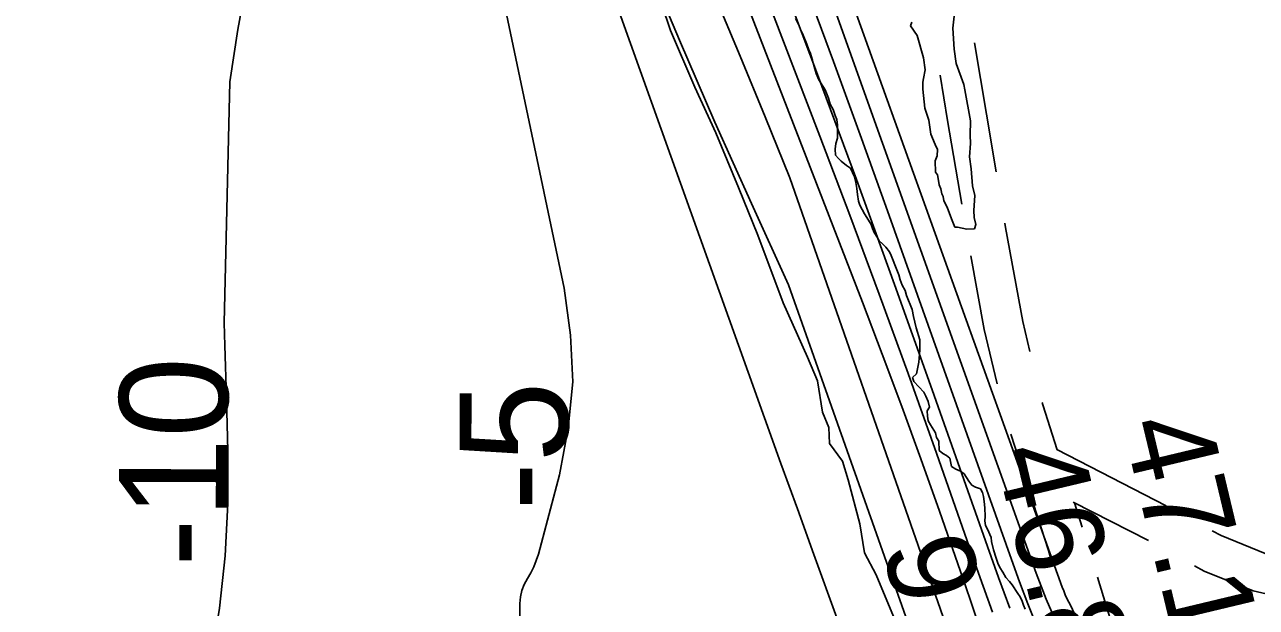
# Model space of a CAD drawing. Extents: x 3250478 to 3288318, y 788638 to 816472.
# Drawn here: x 3278256 to 3279198, y 795831 to 796276 of the extents above; entities that cross this region are included whole.
import ezdxf

# ---------------------------------------------------------------- set-up
doc = ezdxf.new("R2010")
doc.units = 0
for name, color, linetype in [('V-RIVR-EDGE', 7, 'Continuous'), ('V-RIVR-RANG', 7, 'Continuous'), ('V-ROAD-CNTR', 7, 'Continuous'), ('V-SITE-VEGE', 7, 'Continuous'), ('V-TOPO-DPTH', 7, 'Continuous'), ('V-TOPO-MAJR', 7, 'Continuous'), ('V-TOPO-MINR', 7, 'Continuous'), ('V-TOPO-MINR-IDEN', 7, 'Continuous'), ('V-TOPO-WATR', 7, 'Continuous')]:
    doc.layers.add(name, color=color, linetype=linetype)

msp = doc.modelspace()

# ---------------------------------------------------------------- linework, layer by layer
at = {"layer": 'V-RIVR-EDGE'}
msp.add_lwpolyline([(3278928.01, 795805.46), (3278907.27, 795855.5), (3278898.18, 795872.47), (3278894.76, 795894.65), (3278885.71, 795928.14), (3278881.4, 795942.5), (3278871.44, 795956), (3278871.03, 795968.17), (3278866.28, 795979.92), (3278862.43, 796003.83), (3278854.65, 796022.11), (3278836.06, 796063.45), (3278816.63, 796115.23), (3278801.94, 796151.77), (3278784.66, 796193.55), (3278768.66, 796228.36), (3278750.08, 796271.87), (3278730.66, 796329.3)], dxfattribs=at)
at = {"layer": 'V-ROAD-CNTR'}
for p, q in [((3279045.35, 795951.31), (3279129, 795908.39)), ((3279057.85, 795911.18), (3279115.31, 795881.7))]:
    msp.add_line(p, q, dxfattribs=at)
for points in [[(3278982.49, 796262.43), (3278991.43, 796207.89), (3278998.93, 796163.79)], [(3278956.16, 796237.58), (3278961.84, 796202.95), (3278972.72, 796138.96)], [(3279005.63, 796124.36), (3279006.19, 796121.08), (3279019.24, 796049.31), (3279024.75, 796026.23)], [(3278979.61, 796099.56), (3278989.87, 796043.14), (3278999.78, 796001.66)], [(3279034.05, 795987.33), (3279034.49, 795985.47), (3279045.56, 795951.2)], [(3279010.2, 795963.07), (3279038.88, 795874.29), (3279040.83, 795867.87)], [(3279058.69, 795910.54), (3279064.64, 795892.13)], [(3279164.13, 795889.26), (3279170.85, 795885.55), (3279204.47, 795871.99), (3279259.09, 795859.33)], [(3279150.43, 795862.56), (3279157.93, 795858.41), (3279195.42, 795843.29), (3279245.1, 795831.78)], [(3279076.45, 795853.91), (3279103.45, 795765.39), (3279105.45, 795758.21)]]:
    msp.add_lwpolyline(points, dxfattribs=at)
at = {"layer": 'V-SITE-VEGE'}
for p, q in [((3278845.4, 796280.87), (3278848.32, 796275.45)), ((3278933.44, 796275.31), (3278934.43, 796278.04)), ((3278967.18, 796284.97), (3278965.9, 796273.58)), ((3278848.32, 796275.45), (3278849.33, 796272.42)), ((3278849.33, 796272.42), (3278851.29, 796268.2)), ((3278851.29, 796268.2), (3278854.25, 796261.24)), ((3278938.52, 796267.9), (3278933.44, 796275.31)), ((3278943.35, 796250.76), (3278938.52, 796267.9)), ((3278965.9, 796273.58), (3278966.93, 796257.41)), ((3278854.25, 796261.24), (3278855.6, 796257)), ((3278855.6, 796257), (3278856.91, 796254.29)), ((3278966.93, 796257.41), (3278968.33, 796246.65)), ((3278856.91, 796254.29), (3278858.59, 796249.13)), ((3278858.59, 796249.13), (3278859.3, 796246.09)), ((3278944.71, 796241.62), (3278943.35, 796250.76)), ((3278859.3, 796246.09), (3278861.35, 796238.81)), ((3278861.35, 796238.81), (3278863.33, 796233.98)), ((3278943.28, 796235.09), (3278944.71, 796241.62)), ((3278968.33, 796246.65), (3278974.21, 796230.61)), ((3278863.33, 796233.98), (3278866.54, 796229.18)), ((3278866.54, 796229.18), (3278868.15, 796226.47)), ((3278942.82, 796232.38), (3278943.28, 796235.09)), ((3278942.98, 796226.98), (3278942.82, 796232.38)), ((3278974.21, 796230.61), (3278974.88, 796226.31)), ((3278868.15, 796226.47), (3278870.79, 796220.13)), ((3278870.79, 796220.13), (3278872.15, 796215.58)), ((3278944.5, 796212.44), (3278942.98, 796226.98)), ((3278974.88, 796226.31), (3278979.37, 796202.68)), ((3278872.15, 796215.58), (3278874.41, 796211.36)), ((3278874.41, 796211.36), (3278875.77, 796206.81)), ((3278947.47, 796203.34), (3278944.5, 796212.44)), ((3278875.77, 796206.81), (3278877.09, 796203.79)), ((3278877.09, 796203.79), (3278877.52, 796199.52)), ((3278948.88, 796192.58), (3278947.47, 796203.34)), ((3278979.37, 796202.68), (3278979.15, 796191.87)), ((3278877.52, 796199.52), (3278877.65, 796195.24)), ((3278877.65, 796195.24), (3278877.52, 796189.43)), ((3278952.36, 796184.58), (3278948.88, 796192.58)), ((3278979.15, 796191.87), (3278979.35, 796185.39)), ((3278876.42, 796185.42), (3278875.93, 796181.12)), ((3278877.52, 796189.43), (3278876.42, 796185.42)), ((3278954.09, 796180.85), (3278952.36, 796184.58)), ((3278979.35, 796185.39), (3278978.57, 796175.1)), ((3278875.93, 796181.12), (3278876.07, 796176.53)), ((3278876.07, 796176.53), (3278878.29, 796173.84)), ((3278878.29, 796173.84), (3278880.5, 796171.77)), ((3278952.19, 796172.15), (3278953.7, 796175.98)), ((3278952.45, 796163.52), (3278952.19, 796172.15)), ((3278953.7, 796175.98), (3278954.09, 796180.85)), ((3278978.57, 796175.1), (3278979.93, 796165.96)), ((3278880.5, 796171.77), (3278884.57, 796168.52)), ((3278884.57, 796168.52), (3278887.69, 796166.48)), ((3278887.69, 796166.48), (3278890.64, 796159.83)), ((3278954.13, 796161.4), (3278952.45, 796163.52)), ((3278979.93, 796165.96), (3278980.85, 796153.02)), ((3278890.64, 796159.83), (3278891.69, 796155.58)), ((3278891.69, 796155.58), (3278892.44, 796151.01)), ((3278954.8, 796157.1), (3278954.13, 796161.4)), ((3278955.44, 796153.88), (3278954.8, 796157.1)), ((3278956.62, 796150.68), (3278955.44, 796153.88)), ((3278892.44, 796151.01), (3278892.88, 796146.44)), ((3278892.88, 796146.44), (3278893.65, 796141.26)), ((3278957.27, 796146.91), (3278956.62, 796150.68)), ((3278958.41, 796144.79), (3278957.27, 796146.91)), ((3278959.05, 796141.56), (3278958.41, 796144.79)), ((3278980.85, 796153.02), (3278982.7, 796145.51)), ((3278982.7, 796145.51), (3278981.96, 796134.15)), ((3278893.65, 796141.26), (3278894.66, 796138.23)), ((3278894.66, 796138.23), (3278898.22, 796131.6)), ((3278961.35, 796136.77), (3278959.05, 796141.56)), ((3278964.87, 796127.69), (3278961.35, 796136.77)), ((3278898.22, 796131.6), (3278900.14, 796128.91)), ((3278900.14, 796128.91), (3278903.36, 796123.5)), ((3278967.22, 796121.28), (3278964.87, 796127.69)), ((3278981.96, 796134.15), (3278982.12, 796128.75)), ((3278982.12, 796128.75), (3278983.36, 796123.38)), ((3278903.36, 796123.5), (3278904.37, 796120.47)), ((3278904.37, 796120.47), (3278905.69, 796117.45)), ((3278905.69, 796117.45), (3278907.94, 796113.84)), ((3278969.38, 796121.34), (3278967.22, 796121.28)), ((3278976.44, 796119.93), (3278969.38, 796121.34)), ((3278982.38, 796120.11), (3278976.44, 796119.93)), ((3278983.36, 796123.38), (3278982.38, 796120.11)), ((3278907.94, 796113.84), (3278909.56, 796110.83)), ((3278909.56, 796110.83), (3278912.06, 796108.76)), ((3278912.06, 796108.76), (3278914.59, 796106.09)), ((3278914.59, 796106.09), (3278917.46, 796102.5)), ((3278917.46, 796102.5), (3278918.76, 796099.79)), ((3278918.76, 796099.79), (3278923.06, 796088.9)), ((3278923.06, 796088.9), (3278924.41, 796084.96)), ((3278924.41, 796084.96), (3278925.44, 796081.02)), ((3278925.44, 796081.02), (3278927.09, 796077.09)), ((3278927.09, 796077.09), (3278929.36, 796072.87)), ((3278929.36, 796072.87), (3278930.39, 796069.23)), ((3278930.39, 796069.23), (3278934.69, 796058.34)), ((3278934.69, 796058.34), (3278935.76, 796053.18)), ((3278935.76, 796053.18), (3278937.86, 796044.36)), ((3278937.86, 796044.36), (3278940.58, 796035.27)), ((3278940.69, 796031.91), (3278940.52, 796027.31)), ((3278940.58, 796035.27), (3278940.69, 796031.91)), ((3278940.52, 796027.31), (3278939.87, 796018.11)), ((3278939.87, 796018.11), (3278938, 796009.18)), ((3278938, 796009.18), (3278935.03, 796006.34)), ((3278935.03, 796006.34), (3278936.03, 796003.31)), ((3278936.03, 796003.31), (3278943.62, 795995.27)), ((3278943.62, 795995.27), (3278945.24, 795992.27)), ((3278945.24, 795992.27), (3278946.9, 795988.03)), ((3278947.94, 795983.78), (3278946.19, 795980.97)), ((3278946.9, 795988.03), (3278947.94, 795983.78)), ((3278946.19, 795980.97), (3278946.31, 795977)), ((3278946.31, 795977), (3278947.03, 795973.35)), ((3278947.03, 795973.35), (3278948.65, 795970.34)), ((3278948.65, 795970.34), (3278952.51, 795964.03)), ((3278952.51, 795964.03), (3278953.22, 795960.69)), ((3278953.22, 795960.69), (3278955.15, 795957.68)), ((3278955.15, 795957.68), (3278955.36, 795950.65)), ((3278955.36, 795950.65), (3278958.19, 795948.29)), ((3278958.19, 795948.29), (3278960.98, 795946.84)), ((3278960.98, 795946.84), (3278963.49, 795944.78)), ((3278963.49, 795944.78), (3278964.91, 795938.39)), ((3278964.91, 795938.39), (3278968.03, 795936.34)), ((3278968.03, 795936.34), (3278971.74, 795934.92)), ((3278971.74, 795934.92), (3278974.56, 795932.87)), ((3278974.56, 795932.87), (3278978.1, 795927.16)), ((3278978.1, 795927.16), (3278980.33, 795924.17)), ((3278980.33, 795924.17), (3278983.12, 795922.72)), ((3278983.12, 795922.72), (3278986.84, 795921.3)), ((3278986.84, 795921.3), (3278988.45, 795918.59)), ((3278988.45, 795918.59), (3278989.15, 795915.56)), ((3278989.15, 795915.56), (3278989.88, 795911.6)), ((3278989.88, 795911.6), (3278990.33, 795906.72)), ((3278990.53, 795900.3), (3278990.32, 795896.93)), ((3278990.33, 795906.72), (3278990.53, 795900.3)), ((3278990.32, 795896.93), (3278990.74, 795893.27)), ((3278990.74, 795893.27), (3278992.35, 795890.56)), ((3278992.35, 795890.56), (3278994.99, 795884.22)), ((3278994.99, 795884.22), (3278995.39, 795881.17)), ((3278995.39, 795881.17), (3278996.8, 795874.79)), ((3278996.8, 795874.79), (3278998.83, 795868.42)), ((3278998.83, 795868.42), (3279000.17, 795864.48)), ((3279000.17, 795864.48), (3279001.8, 795861.17)), ((3279001.8, 795861.17), (3279004.05, 795857.56)), ((3279004.05, 795857.56), (3279006.31, 795853.65)), ((3279006.31, 795853.65), (3279009.16, 795850.37)), ((3279009.16, 795850.37), (3279011.07, 795847.98)), ((3279011.07, 795847.98), (3279015.55, 795841.39)), ((3279015.55, 795841.39), (3279017.16, 795838.68)), ((3279017.16, 795838.68), (3279018.79, 795835.36)), ((3279018.79, 795835.36), (3279019.8, 795832.33)), ((3279019.8, 795832.33), (3279021.11, 795829.31))]:
    msp.add_line(p, q, dxfattribs=at)
at = {"layer": 'V-TOPO-DPTH'}
for points in [[(3278256.21, 797342.18), (3278275.35, 797265.85), (3278305.03, 797151.19), (3278311.64, 797125.94), (3278318.33, 797100.71), (3278325.16, 797075.51), (3278332.08, 797050.34), (3278404.43, 796789.83), (3278419.79, 796724.19), (3278431.55, 796658.06), (3278437.88, 796591.19), (3278440.59, 796523.83), (3278440.51, 796388.37), (3278419.19, 796272.5), (3278413.15, 796232.57), (3278408.82, 796048.2)], [(3278408.82, 796048.2), (3278413.15, 796232.57), (3278419.19, 796272.5), (3278440.51, 796388.37), (3278440.59, 796523.83), (3278437.88, 796591.19), (3278431.55, 796658.06), (3278419.79, 796724.19), (3278404.43, 796789.83), (3278332.08, 797050.34), (3278325.16, 797075.51), (3278318.33, 797100.71), (3278311.64, 797125.94), (3278305.03, 797151.19), (3278275.35, 797265.85), (3278256.21, 797342.18)], [(3278447.43, 796870.65), (3278485.95, 796794.23), (3278505.7, 796755.1), (3278525.47, 796715.99), (3278545.28, 796676.9), (3278565.12, 796637.83), (3278577, 796614.46), (3278590.65, 796586.95), (3278603.94, 796559.27), (3278616.7, 796531.34), (3278629.1, 796503.24), (3278645.18, 796465.81), (3278649.17, 796456.27), (3278653.05, 796446.68), (3278656.74, 796437.01), (3278660.32, 796427.3), (3278809.31, 796010.55), (3278821.82, 795975.67), (3278834.35, 795940.8), (3278846.95, 795905.96), (3278859.58, 795871.13), (3278877.17, 795822.74)], [(3278447.43, 796870.65), (3278485.95, 796794.23), (3278505.7, 796755.1), (3278525.47, 796715.99), (3278545.28, 796676.9), (3278565.12, 796637.83), (3278577, 796614.46), (3278590.65, 796586.95), (3278603.94, 796559.27), (3278616.7, 796531.34), (3278629.1, 796503.24), (3278645.18, 796465.81), (3278649.17, 796456.27), (3278653.05, 796446.68), (3278656.74, 796437.01), (3278660.32, 796427.3), (3278809.31, 796010.55), (3278821.82, 795975.67), (3278834.35, 795940.8), (3278846.95, 795905.96), (3278859.58, 795871.13), (3278877.17, 795822.74)], [(3279124.26, 795347.76), (3278841.2, 796159.17), (3278822.34, 796205.69), (3278803.22, 796252.1), (3278783.93, 796298.44), (3278760.28, 796354.8), (3278752.57, 796372.86), (3278744.72, 796390.86), (3278736.65, 796408.76), (3278728.44, 796426.59), (3278720.05, 796444.35), (3278711.58, 796462.06), (3278702.98, 796479.71), (3278694.3, 796497.32), (3278630.9, 796624.66), (3278591.38, 796706.33), (3278553.1, 796788.55), (3278516.69, 796871.62)], [(3278408.82, 796048.2), (3278409.32, 796030.93), (3278410.49, 795990.61), (3278411.66, 795950.29), (3278411.5, 795910.07), (3278409.61, 795869.99), (3278405.11, 795830.12), (3278398.88, 795790.39), (3278377.3, 795677.08), (3278388.46, 795413.94), (3278391.9, 795341.73), (3278395.85, 795269.54), (3278400.57, 795197.4), (3278405.8, 795125.29), (3278413.99, 795020.02), (3278415.24, 795000.56), (3278416.12, 794981.09), (3278416.46, 794961.61), (3278416.44, 794942.11), (3278403.87, 794831.33), (3278260.3, 794016.3)], [(3279057.64, 794015.57), (3278260.3, 794016.3), (3278403.87, 794831.33), (3278416.44, 794942.11), (3278416.46, 794961.61), (3278416.12, 794981.09), (3278415.24, 795000.56), (3278413.99, 795020.02), (3278405.8, 795125.29), (3278400.57, 795197.4), (3278395.85, 795269.54), (3278391.9, 795341.73), (3278388.46, 795413.94), (3278377.3, 795677.08), (3278398.88, 795790.39), (3278405.11, 795830.12), (3278409.61, 795869.99), (3278411.5, 795910.07), (3278411.66, 795950.29), (3278410.49, 795990.61), (3278409.32, 796030.93), (3278408.82, 796048.2)]]:
    msp.add_lwpolyline(points, dxfattribs=at)
at = {"layer": 'V-TOPO-MAJR'}
msp.add_lwpolyline([(3279009.39, 795830.14), (3279000.8, 795853.63), (3278992.36, 795877.18), (3278950, 795997), (3278921.22, 796077.55), (3278892.06, 796157.97), (3278862.35, 796238.19), (3278832.27, 796318.27), (3278786.83, 796438), (3278779.1, 796458.08), (3278771.23, 796478.09), (3278763.16, 796498.03), (3278754.96, 796517.92), (3278719.31, 796603.15), (3278692.38, 796665.23), (3278664.36, 796726.8), (3278634.74, 796787.61), (3278604.03, 796847.91)], dxfattribs=at)
at = {"layer": 'V-TOPO-MINR'}
for points in [[(3279349.31, 795186.05), (3279055.96, 795831.78), (3279054.44, 795834.74), (3279053.07, 795837.54), (3279051.78, 795840.37), (3279050.6, 795843.25), (3279049.49, 795846.17), (3278848.07, 796407.24), (3278843.05, 796421.17), (3278838, 796435.1), (3278832.91, 796449.01), (3278827.8, 796462.91), (3278822.65, 796476.8), (3278817.48, 796490.68), (3278812.28, 796504.55), (3278807.06, 796518.41), (3278559.9, 797172.34), (3278391.28, 797782.11)], [(3279148.29, 795205.38), (3278840.15, 796077.38), (3278811.81, 796139.45), (3278783.97, 796201.74), (3278756.91, 796264.37), (3278730.36, 796327.23), (3278695.76, 796410.59), (3278686.79, 796431.9), (3278677.7, 796453.14), (3278668.4, 796474.3), (3278658.97, 796495.39), (3278627.19, 796565.57), (3278601.62, 796621.64), (3278575.84, 796677.62), (3278549.75, 796733.45), (3278523.45, 796789.18), (3278367.78, 797116.74), (3278288.44, 797503.93)], [(3278408.82, 796048.2), (3278413.15, 796232.57), (3278419.19, 796272.5), (3278440.51, 796388.37), (3278440.59, 796523.83), (3278437.88, 796591.19), (3278431.55, 796658.06), (3278419.79, 796724.19), (3278404.43, 796789.83), (3278332.08, 797050.34), (3278325.16, 797075.51), (3278318.33, 797100.71), (3278311.64, 797125.94), (3278305.03, 797151.19), (3278275.35, 797265.85), (3278256.21, 797342.18)], [(3279041.45, 795827.05), (3279037.27, 795836.91), (3279033.36, 795846.87), (3279029.63, 795856.9), (3278883.08, 796267.04), (3278869.89, 796303.72), (3278856.6, 796340.37), (3278843.15, 796376.97), (3278829.61, 796413.53), (3278828.56, 796416.35), (3278815.36, 796451.43), (3278802.02, 796486.45), (3278788.45, 796521.39), (3278774.74, 796556.27), (3278641.92, 796891.12)], [(3279124.26, 795347.76), (3278841.2, 796159.17), (3278822.34, 796205.69), (3278803.22, 796252.1), (3278783.93, 796298.44), (3278760.28, 796354.8), (3278752.57, 796372.86), (3278744.72, 796390.86), (3278736.65, 796408.76), (3278728.44, 796426.59), (3278720.05, 796444.35), (3278711.58, 796462.06), (3278702.98, 796479.71), (3278694.3, 796497.32), (3278630.9, 796624.66), (3278591.38, 796706.33), (3278553.1, 796788.55), (3278516.69, 796871.62)], [(3278634.63, 795777.32), (3278634.82, 795833.63), (3278635.29, 795838.69), (3278636.31, 795843.58), (3278638.16, 795848.21), (3278640.57, 795852.68), (3278643.2, 795857.12), (3278645.52, 795861.7), (3278647.38, 795866.48), (3278648.94, 795871.39), (3278665.05, 795932.16), (3278671.81, 795967.64), (3278675.23, 796003.19), (3278673.64, 796038.88), (3278668.72, 796074.65), (3278605.89, 796372.99), (3278599.03, 796401.59), (3278591.13, 796429.86), (3278581.66, 796457.65), (3278571.15, 796485.12), (3278515.51, 796619.22), (3278483.01, 796699.45), (3278451.43, 796780.03), (3278421.21, 796861.13)], [(3279029.77, 795816.75), (3279023.12, 795833.48), (3279016.75, 795850.33), (3279010.58, 795867.24), (3278917.04, 796130.39), (3278895.93, 796189.27), (3278874.6, 796248.06), (3278852.96, 796306.75), (3278831.1, 796365.35), (3278807.87, 796427.13), (3278797.34, 796454.73), (3278786.64, 796482.27), (3278775.69, 796509.7), (3278764.56, 796537.07), (3278706.54, 796677.93), (3278673.08, 796757.93), (3278639.07, 796837.69)], [(3278996.14, 795826.91), (3278985.53, 795856.8), (3278974.97, 795886.71), (3278953.2, 795948.66), (3278931.55, 796009.47), (3278909.56, 796070.16), (3278887.06, 796130.66), (3278864.22, 796191.03), (3278765.38, 796449.01), (3278760.54, 796461.46), (3278755.63, 796473.88), (3278750.59, 796486.25), (3278745.48, 796498.59), (3278723.55, 796550.8), (3278706.95, 796589.01), (3278689.74, 796626.93), (3278671.6, 796664.42), (3278652.85, 796701.61), (3278635.1, 796735.77), (3278613.16, 796777.79), (3278591.12, 796819.75)], [(3278983.51, 795823.84), (3278979.62, 795835.07), (3278975.72, 795846.29), (3278955.5, 795904.22), (3278941.28, 795944.33), (3278926.78, 795984.35), (3278911.89, 796024.21), (3278896.74, 796063.98), (3278743.46, 796460.17)], [(3278260.3, 794016.3), (3278403.87, 794831.33), (3278416.44, 794942.11), (3278416.46, 794961.61), (3278416.12, 794981.09), (3278415.24, 795000.56), (3278413.99, 795020.02), (3278405.8, 795125.29), (3278400.57, 795197.4), (3278395.85, 795269.54), (3278391.9, 795341.73), (3278388.46, 795413.94), (3278377.3, 795677.08), (3278398.88, 795790.39), (3278405.11, 795830.12), (3278409.61, 795869.99), (3278411.5, 795910.07), (3278411.66, 795950.29), (3278410.49, 795990.61), (3278409.32, 796030.93), (3278408.82, 796048.2)]]:
    msp.add_lwpolyline(points, dxfattribs=at)
at = {"layer": 'V-TOPO-WATR'}
msp.add_lwpolyline([(3278877.17, 795822.74), (3278859.58, 795871.13), (3278846.95, 795905.96), (3278834.35, 795940.8), (3278821.82, 795975.67), (3278809.31, 796010.55), (3278660.32, 796427.3), (3278656.74, 796437.01), (3278653.05, 796446.68), (3278649.17, 796456.27), (3278645.18, 796465.81), (3278629.1, 796503.24), (3278616.7, 796531.34), (3278603.94, 796559.27), (3278590.65, 796586.95), (3278577, 796614.46), (3278565.12, 796637.83), (3278545.28, 796676.9), (3278525.47, 796715.99), (3278505.7, 796755.1), (3278485.95, 796794.23), (3278447.43, 796870.65)], dxfattribs=at)

# ---------------------------------------------------------------- texts
at = {"layer": 'V-RIVR-RANG'}
for s, rotation, p in [('47.1', 283.44833, (3279095.22, 795970.6)), ('46.8', 283.44833, (3278997.47, 795949.42)), ('9.9', 283.72686, (3278911.64, 795876.95))]:
    msp.add_text(s, height=67, rotation=rotation, dxfattribs=at).set_placement(p)
at = {"layer": 'V-TOPO-MINR-IDEN'}
for s, p in [('-10', (3278411.15, 795861.52)), ('-5', (3278671.56, 795904.57))]:
    msp.add_text(s, height=83, rotation=89.77589, dxfattribs=at).set_placement(p)

doc.saveas('drawing.dxf')
